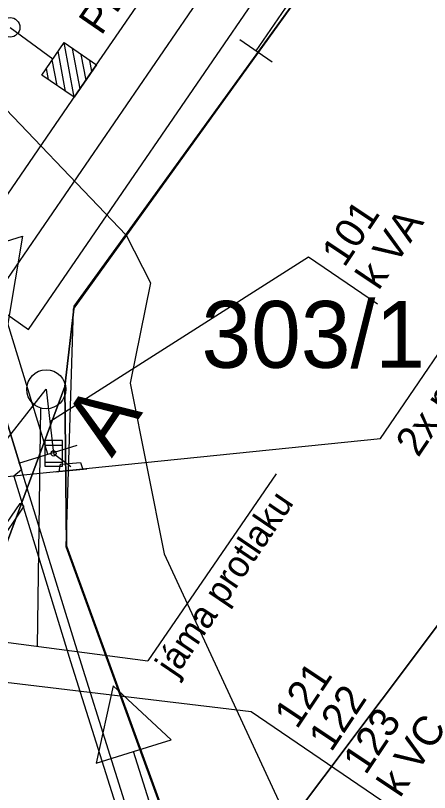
# Model space of a CAD drawing. Extents: x -558199 to -558019, y -1073463 to -1073248.
# Drawn here: x -558136.35 to -558125.81, y -1073413.56 to -1073393.79 of the extents above; entities that cross this region are included whole.
import ezdxf

# ---------------------------------------------------------------- set-up
doc = ezdxf.new("R2010")
doc.units = 0
for name, color, linetype in [('Default', 7, 'Continuous'), ('El2015-Svršek - součást', 7, 'Continuous'), ('El2015-Zabzař nadzemní', 7, 'Continuous'), ('GasNet', 7, 'Continuous'), ('Kolej', 7, 'Continuous'), ('Komunikace', 7, 'Continuous'), ('Nová kabelizace', 7, 'Continuous'), ('nové prvky ZZ', 7, 'Continuous'), ('Návěst místo trati', 7, 'Continuous'), ('Plot - zábradlí', 7, 'Continuous'), ('PS01_PS02_nové prvky ZZ', 7, 'Continuous'), ('Přejezd - štěrkové lože', 7, 'Continuous'), ('Svazek obcí údolí Desné', 7, 'Continuous'), ('Svazek obcí-zabezpečovací_nadzemní', 7, 'Continuous'), ('Vrstva 15', 7, 'Continuous'), ('Vrstva 18', 7, 'Continuous'), ('zab zař nové popis a prvky', 7, 'Continuous')]:
    doc.layers.add(name, color=color, linetype=linetype)

msp = doc.modelspace()

# ---------------------------------------------------------------- linework, layer by layer
at = {"layer": 'Default'}
msp.add_line((-558129.715, -1073405.451), (-558132.976, -1073410.212), dxfattribs=at)
msp.add_lwpolyline([(-558130.328, -1073420.145), (-558131.489, -1073419.211), (-558132.265, -1073417.928), (-558133.167, -1073415.078), (-558134.705, -1073410.166), (-558136.19, -1073405.354), (-558137.19, -1073402.13), (-558138.301, -1073398.037), (-558138.619, -1073396.923), (-558140.033, -1073392.586), (-558141.446, -1073388.086), (-558141.737, -1073387.169), (-558144.083, -1073379.873)], dxfattribs=at)
at = {"layer": 'El2015-Svršek - součást'}
for p, q in [((-558134.852, -1073395.872), (-558135.11, -1073394.482)), ((-558134.702, -1073395.654), (-558134.892, -1073394.632)), ((-558135.07, -1073395.722), (-558135.26, -1073394.7)), ((-558134.551, -1073395.435), (-558134.673, -1073394.782)), ((-558135.289, -1073395.572), (-558135.41, -1073394.919)), ((-558134.401, -1073395.216), (-558134.454, -1073394.932)), ((-558135.507, -1073395.422), (-558135.56, -1073395.138))]:
    msp.add_line(p, q, dxfattribs=at)
msp.add_lwpolyline([(-558135.676, -1073395.306), (-558135.11, -1073394.482), (-558134.286, -1073395.048), (-558134.852, -1073395.872)], close=True, dxfattribs=at)
at = {"layer": 'El2015-Zabzař nadzemní'}
msp.add_circle((-558136.485, -1073394.093), 0.25, dxfattribs=at)
at = {"layer": 'GasNet'}
msp.add_lwpolyline([(-558154.956, -1073358.252), (-558154.85, -1073358.61), (-558153.29, -1073363.26), (-558150.04, -1073372.31), (-558146.13, -1073372.89), (-558143.51, -1073381.67), (-558141.19, -1073387.87), (-558138.86, -1073392.55), (-558137.31, -1073395.43), (-558133.53, -1073399.38), (-558132.91, -1073400.59), (-558133.43, -1073403.15), (-558132.56, -1073407.49), (-558129.22, -1073414.7), (-558126.32, -1073420.06)], dxfattribs=at)
at = {"layer": 'Kolej'}
msp.add_lwpolyline([(-558166.192, -1073441.436), (-558164.779, -1073439.38), (-558155.66, -1073426.127), (-558147.216, -1073413.854), (-558143.692, -1073408.727), (-558141.06, -1073404.904), (-558137.302, -1073399.438), (-558134.569, -1073395.461), (-558131.717, -1073391.307), (-558124.893, -1073381.375), (-558115.4, -1073367.564), (-558109.636, -1073359.184)], dxfattribs=at)
at = {"layer": 'Komunikace'}
for points in [[(-558107.659, -1073360.546), (-558114.342, -1073368.192), (-558123.867, -1073381.998), (-558130.695, -1073391.932), (-558136.982, -1073401.101), (-558136.018, -1073401.785), (-558129.729, -1073392.612), (-558122.956, -1073382.764), (-558113.3, -1073368.807), (-558106.77, -1073361.159)], [(-558134.582, -1073423.154), (-558136.753, -1073416.165), (-558138.246, -1073411.366), (-558139.293, -1073408.016), (-558139.888, -1073406.031), (-558138.651, -1073404.246), (-558137.19, -1073402.13), (-558136.19, -1073405.354), (-558136.385, -1073405.515), (-558134.943, -1073410.228), (-558133.406, -1073415.122), (-558132.477, -1073418.012), (-558131.667, -1073419.37), (-558130.464, -1073420.348)], [(-558130.328, -1073420.145), (-558131.489, -1073419.211), (-558132.265, -1073417.928), (-558133.167, -1073415.078), (-558134.705, -1073410.166), (-558136.19, -1073405.354)], [(-558132.744, -1073414.431), (-558133.34, -1073412.522), (-558132.385, -1073412.224), (-558133.86, -1073410.851), (-558134.294, -1073412.82), (-558133.34, -1073412.522)]]:
    msp.add_lwpolyline(points, dxfattribs=at)
at = {"layer": 'Nová kabelizace'}
msp.add_lwpolyline([(-558145.224, -1073405.842), (-558140.251, -1073409.265), (-558135.564, -1073403.303), (-558135.378, -1073404.935)], dxfattribs=at)
at = {"layer": 'nové prvky ZZ'}
for p, q in [((-558135.378, -1073404.935), (-558134.942, -1073405.27)), ((-558135.331, -1073405.403), (-558134.534, -1073405.331)), ((-558136.235, -1073406.21), (-558139.648, -1073411.145)), ((-558136.135, -1073406.278), (-558139.483, -1073411.258)), ((-558136.135, -1073406.278), (-558136.235, -1073406.21))]:
    msp.add_line(p, q, dxfattribs=at)
for points in [[(-558135.603, -1073404.61), (-558135.603, -1073405.26), (-558135.153, -1073405.26), (-558135.153, -1073404.61)], [(-558135.603, -1073404.735), (-558135.603, -1073405.16), (-558135.153, -1073405.16), (-558135.153, -1073404.735)], [(-558135.232, -1073405.394), (-558135.203, -1073405.211), (-558134.695, -1073405.165), (-558134.634, -1073405.34)]]:
    msp.add_lwpolyline(points, close=True, dxfattribs=at)
msp.add_circle((-558135.378, -1073404.935), 0.0675, dxfattribs=at)
msp.add_circle((-558135.378, -1073404.935), 0.0675, dxfattribs=at)
msp.add_circle((-558135.378, -1073404.935), 0.0675, dxfattribs=at)
at = {"layer": 'Návěst místo trati'}
for p, q in [((-558128.526, -1073392.214), (-558130.225, -1073394.686)), ((-558130.637, -1073394.403), (-558129.813, -1073394.969))]:
    msp.add_line(p, q, dxfattribs=at)
at = {"layer": 'Plot - zábradlí'}
for points in [[(-558134.866, -1073401.264), (-558123.308, -1073385.212), (-558113.281, -1073375.056), (-558109.254, -1073378.581)], [(-558130.927, -1073418.673), (-558135.055, -1073407.314), (-558134.866, -1073401.264)]]:
    msp.add_lwpolyline(points, dxfattribs=at)
at = {"layer": 'Přejezd - štěrkové lože'}
msp.add_line((-558136.264, -1073405.18), (-558134.775, -1073404.727), dxfattribs=at)
msp.add_line((-558136.264, -1073405.18), (-558134.775, -1073404.727), dxfattribs=at)
msp.add_lwpolyline([(-558135.52, -1073404.953), (-558136.542, -1073401.63), (-558138.075, -1073400.003), (-558136.167, -1073399.41), (-558136.542, -1073401.63)], dxfattribs=at)
msp.add_lwpolyline([(-558135.52, -1073404.953), (-558136.542, -1073401.63), (-558138.075, -1073400.003), (-558136.167, -1073399.41), (-558136.542, -1073401.63)], dxfattribs=at)
at = {"layer": 'Svazek obcí údolí Desné'}
msp.add_lwpolyline([(-558100.193, -1073365.689), (-558100.88, -1073366.68), (-558101.24, -1073366.41), (-558106.08, -1073373.34), (-558109.37, -1073371.06), (-558120.48, -1073382.36), (-558123.3, -1073385.22), (-558134.85, -1073401.19), (-558135.09, -1073403.23), (-558138.47, -1073412.32), (-558161.279, -1073444.82)], dxfattribs=at)
msp.add_lwpolyline([(-558135.09, -1073403.23), (-558134.85, -1073401.19), (-558123.3, -1073385.22), (-558120.48, -1073382.36), (-558110.68, -1073389.44), (-558131.47, -1073417.12), (-558135.05, -1073407.29)], close=True, dxfattribs=at)
at = {"layer": 'Svazek obcí-zabezpečovací_nadzemní'}
msp.add_line((-558136.485, -1073394.093), (-558135.393, -1073394.894), dxfattribs=at)
at = {"layer": 'Vrstva 15'}
msp.add_lwpolyline([(-558100.193, -1073365.689), (-558100.88, -1073366.68), (-558101.24, -1073366.41), (-558106.08, -1073373.34), (-558109.37, -1073371.06), (-558120.48, -1073382.36), (-558123.3, -1073385.22), (-558134.85, -1073401.19), (-558135.09, -1073403.23), (-558138.47, -1073412.32), (-558161.279, -1073444.82)], dxfattribs=at)
for points in [[(-558135.09, -1073403.23), (-558134.85, -1073401.19), (-558123.3, -1073385.22), (-558120.48, -1073382.36), (-558110.68, -1073389.44), (-558131.47, -1073417.12), (-558135.05, -1073407.29)], [(-558110.24, -1073388.85), (-558106.42, -1073391.52), (-558126.94, -1073419.09), (-558130.91, -1073418.65), (-558131.47, -1073417.12), (-558110.68, -1073389.44)], [(-558138.47, -1073412.32), (-558135.09, -1073403.23), (-558135.05, -1073407.29), (-558131.47, -1073417.12), (-558130.91, -1073418.65), (-558126.8, -1073426.64), (-558129.35, -1073429.91), (-558131.5, -1073432.67), (-558132.91, -1073428.56)]]:
    msp.add_lwpolyline(points, close=True, dxfattribs=at)
at = {"layer": 'zab zař nové popis a prvky'}
for p, q in [((-558127.057, -1073404.553), (-558117.656, -1073390.755)), ((-558135.471, -1073404.119), (-558128.886, -1073399.932)), ((-558128.886, -1073399.932), (-558127.134, -1073401.125)), ((-558137.377, -1073405.609), (-558127.057, -1073404.553)), ((-558139.991, -1073410.353), (-558130.352, -1073411.501)), ((-558130.352, -1073411.501), (-558126.649, -1073414.025))]:
    msp.add_line(p, q, dxfattribs=at)
for points in [[(-558135.788, -1073409.842), (-558135.701, -1073403.782)], [(-558139.755, -1073409.322), (-558132.976, -1073410.212)]]:
    msp.add_lwpolyline(points, dxfattribs=at)
msp.add_circle((-558135.564, -1073403.303), 0.498, dxfattribs=at)

# ---------------------------------------------------------------- texts
at = {"layer": 'El2015-Zabzař nadzemní'}
msp.add_text('PB8PL', height=0.75, rotation=55.5278, dxfattribs=at).set_placement((-558134.163, -1073394.321))
at = {"layer": 'PS01_PS02_nové prvky ZZ'}
msp.add_text('A', height=1.6, rotation=55.7527, dxfattribs=at).set_placement((-558133.896, -1073405.069))
at = {"layer": 'Vrstva 18'}
msp.add_text('303/1', height=1.7, dxfattribs=at).set_placement((-558131.613, -1073402.756))
at = {"layer": 'zab zař nové popis a prvky'}
for s, height, rotation, p in [('2x protlak hloubky min. 120 cm-8m', 0.75, 55.9321, (-558126.098, -1073405.057)), ('101', 0.75, 56.3059, (-558127.978, -1073400.225)), ('k VA', 0.75, 56.3059, (-558127.105, -1073400.808)), ('jáma protlaku', 0.672, 55.8269, (-558132.273, -1073410.653)), ('121', 0.75, 56.3059, (-558129.182, -1073411.976)), ('122', 0.75, 56.3059, (-558128.309, -1073412.558)), ('123', 0.75, 56.3059, (-558127.435, -1073413.141)), ('k VC', 0.75, 56.3059, (-558126.561, -1073413.723))]:
    msp.add_text(s, height=height, rotation=rotation, dxfattribs=at).set_placement(p)

doc.saveas('drawing.dxf')
